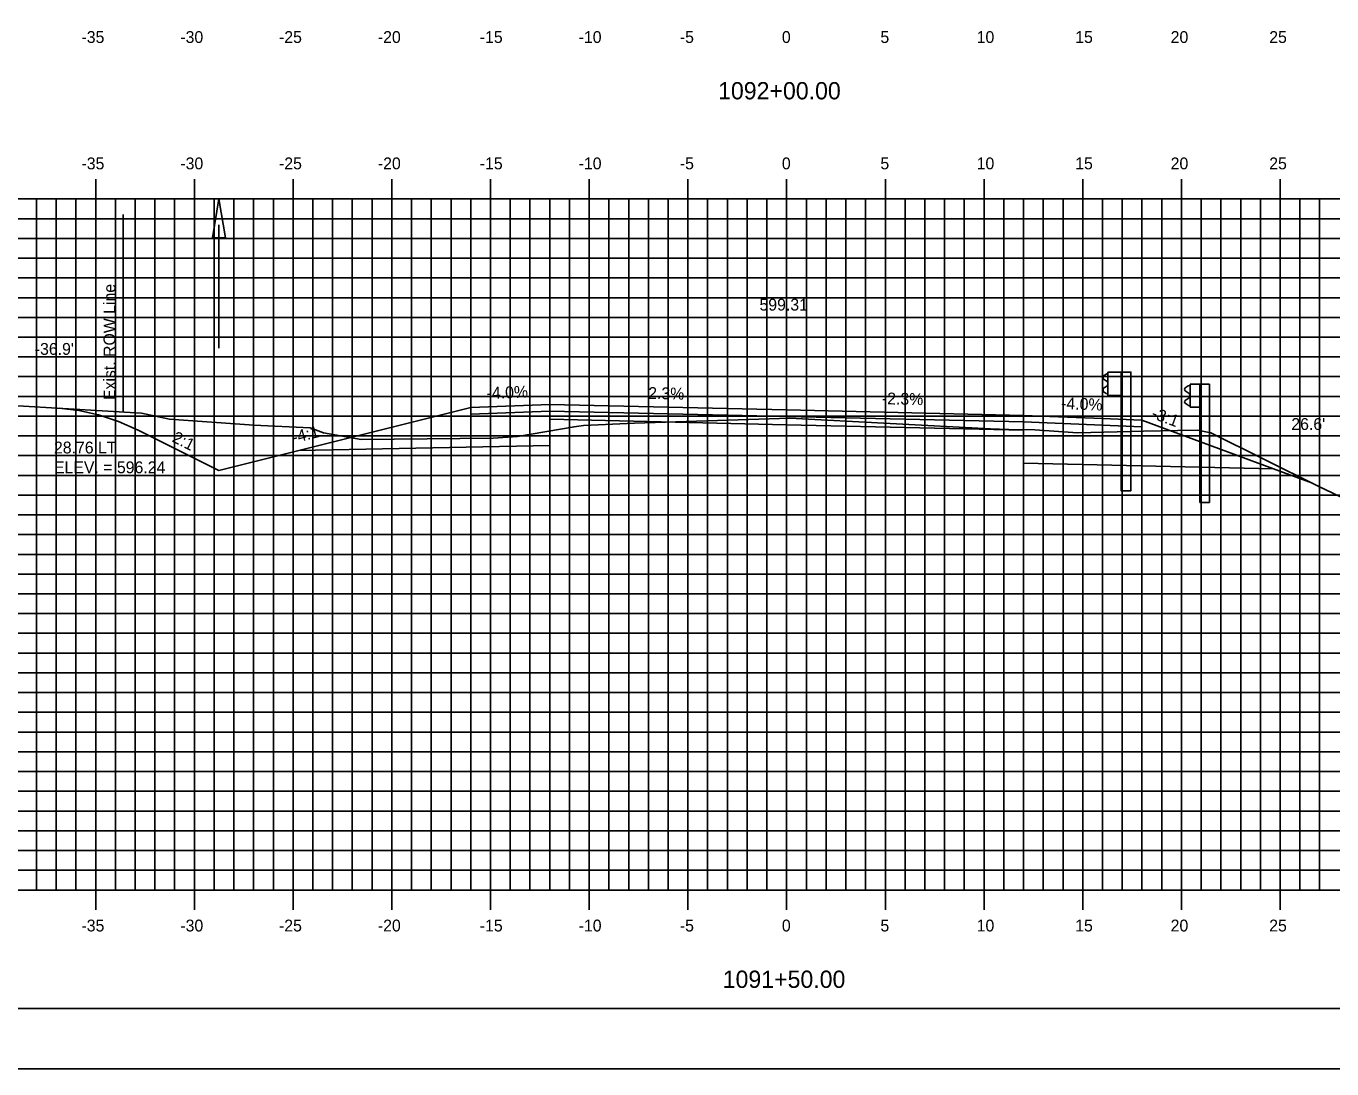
# Model space of a CAD drawing. Extents: x 1073864 to 1074034, y 779716 to 779826.
# Drawn here: x 1073908.9 to 1073975.1, y 779715.6 to 779768.5 of the extents above; entities that cross this region are included whole.
import ezdxf

# ---------------------------------------------------------------- set-up
doc = ezdxf.new("R2010")
doc.units = 0
for name, color, linetype in [('ANNOTATION', 7, 'Continuous'), ('BORDER', 7, 'Continuous'), ('D_Drainage_Ditch_Line', 7, 'Continuous'), ('D_Guardrail_Beam_Rt', 7, 'Continuous'), ('D_Roadway_Centerline', 7, 'Continuous'), ('D_Roadway_Centerline_Text', 7, 'Continuous'), ('D_Roadway_Edge_Pavement', 7, 'Continuous'), ('D_Roadway_Edge_Shoulder', 7, 'Continuous'), ('D_Roadway_Pavement', 7, 'Continuous'), ('D_Roadway_SlopeLines', 7, 'Continuous'), ('D_Roadway_SubGrade', 7, 'Continuous'), ('D_Text_Standard', 7, 'Continuous'), ('E_ROW_Line', 7, 'Continuous'), ('H_V ANNOTATION', 7, 'Continuous'), ('M_Guardrail', 7, 'Continuous'), ('MAJOR', 7, 'Continuous'), ('MINOR', 7, 'Continuous'), ('PLOT BOUNDARY', 7, 'Continuous'), ('S_Guardrail_Beam', 7, 'Continuous'), ('S_Roadway_Centerline', 7, 'Continuous')]:
    doc.layers.add(name, color=color, linetype=linetype)

msp = doc.modelspace()

# ---------------------------------------------------------------- linework, layer by layer
at = {"layer": 'BORDER'}
msp.add_lwpolyline([(1073872.472, 779718.706), (1074032.472, 779718.706), (1074032.472, 779823.706), (1073872.472, 779823.706)], close=True, dxfattribs=at)
at = {"layer": 'D_Drainage_Ditch_Line'}
msp.add_line((1073918.712, 779758.393), (1073918.712, 779752.15), dxfattribs=at)
msp.add_lwpolyline([(1073919.04, 779757.737), (1073918.384, 779757.737), (1073918.712, 779759.706)], close=True, dxfattribs=at)
at = {"layer": 'D_Guardrail_Beam_Rt'}
msp.add_lwpolyline([(1073963.751, 779750.856), (1073963.669, 779750.841), (1073963.652, 779750.834), (1073963.509, 779750.734), (1073963.509, 779750.591), (1073963.704, 779750.454), (1073963.738, 779750.39), (1073963.738, 779750.299), (1073963.704, 779750.234), (1073963.509, 779750.098), (1073963.509, 779749.954), (1073963.652, 779749.854), (1073963.669, 779749.847), (1073963.751, 779749.833)], dxfattribs=at)
for points in [[(1073963.751, 779750.935), (1073964.417, 779750.935), (1073964.417, 779749.754), (1073963.751, 779749.754)], [(1073964.417, 779750.935), (1073964.91, 779750.935), (1073964.91, 779744.931), (1073964.417, 779744.931)]]:
    msp.add_lwpolyline(points, close=True, dxfattribs=at)
at = {"layer": 'D_Roadway_Centerline'}
for points in [[(1073931.472, 779749.136), (1073935.472, 779749.296), (1073947.472, 779749.02), (1073959.472, 779748.744), (1073963.472, 779748.584), (1073965.472, 779748.504)], [(1073918.712, 779745.946), (1073922.762, 779746.958)]]:
    msp.add_lwpolyline(points, dxfattribs=at)
at = {"layer": 'D_Roadway_Edge_Pavement'}
msp.add_lwpolyline([(1073935.472, 779748.962), (1073935.472, 779749.296), (1073947.472, 779749.02), (1073959.472, 779748.744), (1073959.472, 779748.41), (1073947.472, 779748.686)], close=True, dxfattribs=at)
at = {"layer": 'D_Roadway_Edge_Shoulder'}
msp.add_lwpolyline([(1073935.472, 779749.296), (1073931.472, 779749.136), (1073931.472, 779748.802), (1073935.472, 779748.962)], close=True, dxfattribs=at)
msp.add_lwpolyline([(1073959.472, 779748.744), (1073963.472, 779748.584), (1073965.472, 779748.504), (1073965.472, 779748.17), (1073959.472, 779748.41), (1073959.472, 779748.744)], dxfattribs=at)
at = {"layer": 'D_Roadway_Pavement'}
msp.add_lwpolyline([(1073935.472, 779748.546), (1073935.472, 779748.962), (1073947.472, 779748.686), (1073959.472, 779748.41), (1073959.472, 779747.994), (1073947.472, 779748.27)], close=True, dxfattribs=at)
msp.add_lwpolyline([(1073935.472, 779748.962), (1073935.472, 779748.546)], dxfattribs=at)
at = {"layer": 'D_Roadway_SlopeLines'}
for points in [[(1073918.712, 779745.946), (1073914.62, 779747.992), (1073913.62, 779748.437), (1073912.62, 779748.771), (1073911.62, 779748.996), (1073910.62, 779749.11)], [(1073935.472, 779749.296), (1073931.472, 779749.136)], [(1073965.472, 779748.504), (1073972.136, 779746.036), (1073974.106, 779745.306)]]:
    msp.add_lwpolyline(points, dxfattribs=at)
at = {"layer": 'D_Roadway_SubGrade'}
msp.add_lwpolyline([(1073935.472, 779748.962), (1073931.472, 779748.802), (1073931.472, 779749.136), (1073922.762, 779746.958), (1073935.472, 779747.212), (1073935.472, 779748.962)], close=True, dxfattribs=at)
msp.add_lwpolyline([(1073972.136, 779746.036), (1073959.472, 779746.327), (1073959.472, 779746.91), (1073959.472, 779748.41), (1073959.472, 779748.41), (1073965.472, 779748.17), (1073965.472, 779748.504)], dxfattribs=at)
at = {"layer": 'E_ROW_Line'}
msp.add_line((1073913.87, 779748.918), (1073913.87, 779758.918), dxfattribs=at)
msp.add_line((1073913.87, 779748.918), (1073913.87, 779758.918), dxfattribs=at)
at = {"layer": 'M_Guardrail'}
for p, q in [((1073968.397, 779750.328), (1073968.888, 779750.328)), ((1073968.888, 779750.328), (1073968.888, 779744.328)), ((1073968.397, 779744.328), (1073968.397, 779749.161)), ((1073968.397, 779744.328), (1073968.888, 779744.328))]:
    msp.add_line(p, q, dxfattribs=at)
at = {"layer": 'MAJOR'}
for p, q in [((1073912.472, 779760.708), (1073912.472, 779759.706)), ((1073917.472, 779760.708), (1073917.472, 779759.706)), ((1073922.472, 779760.708), (1073922.472, 779759.706)), ((1073927.472, 779760.708), (1073927.472, 779759.706)), ((1073932.472, 779760.708), (1073932.472, 779759.706)), ((1073937.472, 779760.708), (1073937.472, 779759.706)), ((1073942.472, 779760.708), (1073942.472, 779759.706)), ((1073947.472, 779760.708), (1073947.472, 779759.706)), ((1073952.472, 779760.708), (1073952.472, 779759.706)), ((1073957.472, 779760.708), (1073957.472, 779759.706)), ((1073962.472, 779760.708), (1073962.472, 779759.706)), ((1073967.472, 779760.708), (1073967.472, 779759.706)), ((1073972.472, 779760.708), (1073972.472, 779759.706)), ((1073877.472, 779759.706), (1074017.472, 779759.706)), ((1073877.472, 779759.706), (1074017.472, 779759.706)), ((1073912.472, 779724.706), (1073912.472, 779759.706)), ((1073917.472, 779724.706), (1073917.472, 779759.706)), ((1073922.472, 779724.706), (1073922.472, 779759.706)), ((1073927.472, 779724.706), (1073927.472, 779759.706)), ((1073932.472, 779724.706), (1073932.472, 779759.706)), ((1073937.472, 779724.706), (1073937.472, 779759.706)), ((1073942.472, 779724.706), (1073942.472, 779759.706)), ((1073947.472, 779724.706), (1073947.472, 779759.706)), ((1073952.472, 779724.706), (1073952.472, 779759.706)), ((1073957.472, 779724.706), (1073957.472, 779759.706)), ((1073962.472, 779724.706), (1073962.472, 779759.706)), ((1073967.472, 779724.706), (1073967.472, 779759.706)), ((1073972.472, 779724.706), (1073972.472, 779759.706)), ((1073877.472, 779754.706), (1074017.472, 779754.706)), ((1073877.472, 779749.706), (1074017.472, 779749.706)), ((1073877.472, 779744.706), (1074017.472, 779744.706)), ((1073877.472, 779739.706), (1074017.472, 779739.706)), ((1073877.472, 779734.706), (1074017.472, 779734.706)), ((1073877.472, 779729.706), (1074017.472, 779729.706)), ((1073877.472, 779724.706), (1074017.472, 779724.706)), ((1073877.472, 779724.706), (1074017.472, 779724.706)), ((1073912.472, 779723.704), (1073912.472, 779724.706)), ((1073917.472, 779723.704), (1073917.472, 779724.706)), ((1073922.472, 779723.704), (1073922.472, 779724.706)), ((1073927.472, 779723.704), (1073927.472, 779724.706)), ((1073932.472, 779723.704), (1073932.472, 779724.706)), ((1073937.472, 779723.704), (1073937.472, 779724.706)), ((1073942.472, 779723.704), (1073942.472, 779724.706)), ((1073947.472, 779723.704), (1073947.472, 779724.706)), ((1073952.472, 779723.704), (1073952.472, 779724.706)), ((1073957.472, 779723.704), (1073957.472, 779724.706)), ((1073962.472, 779723.704), (1073962.472, 779724.706)), ((1073967.472, 779723.704), (1073967.472, 779724.706)), ((1073972.472, 779723.704), (1073972.472, 779724.706))]:
    msp.add_line(p, q, dxfattribs=at)
at = {"layer": 'MINOR'}
for p, q in [((1073909.472, 779724.706), (1073909.472, 779759.706)), ((1073910.472, 779724.706), (1073910.472, 779759.706)), ((1073911.472, 779724.706), (1073911.472, 779759.706)), ((1073913.472, 779724.706), (1073913.472, 779759.706)), ((1073914.472, 779724.706), (1073914.472, 779759.706)), ((1073915.472, 779724.706), (1073915.472, 779759.706)), ((1073916.472, 779724.706), (1073916.472, 779759.706)), ((1073918.472, 779724.706), (1073918.472, 779759.706)), ((1073919.472, 779724.706), (1073919.472, 779759.706)), ((1073920.472, 779724.706), (1073920.472, 779759.706)), ((1073921.472, 779724.706), (1073921.472, 779759.706)), ((1073923.472, 779724.706), (1073923.472, 779759.706)), ((1073924.472, 779724.706), (1073924.472, 779759.706)), ((1073925.472, 779724.706), (1073925.472, 779759.706)), ((1073926.472, 779724.706), (1073926.472, 779759.706)), ((1073928.472, 779724.706), (1073928.472, 779759.706)), ((1073929.472, 779724.706), (1073929.472, 779759.706)), ((1073930.472, 779724.706), (1073930.472, 779759.706)), ((1073931.472, 779724.706), (1073931.472, 779759.706)), ((1073933.472, 779724.706), (1073933.472, 779759.706)), ((1073934.472, 779724.706), (1073934.472, 779759.706)), ((1073935.472, 779724.706), (1073935.472, 779759.706)), ((1073936.472, 779724.706), (1073936.472, 779759.706)), ((1073938.472, 779724.706), (1073938.472, 779759.706)), ((1073939.472, 779724.706), (1073939.472, 779759.706)), ((1073940.472, 779724.706), (1073940.472, 779759.706)), ((1073941.472, 779724.706), (1073941.472, 779759.706)), ((1073943.472, 779724.706), (1073943.472, 779759.706)), ((1073944.472, 779724.706), (1073944.472, 779759.706)), ((1073945.472, 779724.706), (1073945.472, 779759.706)), ((1073946.472, 779724.706), (1073946.472, 779759.706)), ((1073948.472, 779724.706), (1073948.472, 779759.706)), ((1073949.472, 779724.706), (1073949.472, 779759.706)), ((1073950.472, 779724.706), (1073950.472, 779759.706)), ((1073951.472, 779724.706), (1073951.472, 779759.706)), ((1073953.472, 779724.706), (1073953.472, 779759.706)), ((1073954.472, 779724.706), (1073954.472, 779759.706)), ((1073955.472, 779724.706), (1073955.472, 779759.706)), ((1073956.472, 779724.706), (1073956.472, 779759.706)), ((1073958.472, 779724.706), (1073958.472, 779759.706)), ((1073959.472, 779724.706), (1073959.472, 779759.706)), ((1073960.472, 779724.706), (1073960.472, 779759.706)), ((1073961.472, 779724.706), (1073961.472, 779759.706)), ((1073963.472, 779724.706), (1073963.472, 779759.706)), ((1073964.472, 779724.706), (1073964.472, 779759.706)), ((1073965.472, 779724.706), (1073965.472, 779759.706)), ((1073966.472, 779724.706), (1073966.472, 779759.706)), ((1073968.472, 779724.706), (1073968.472, 779759.706)), ((1073969.472, 779724.706), (1073969.472, 779759.706)), ((1073970.472, 779724.706), (1073970.472, 779759.706)), ((1073971.472, 779724.706), (1073971.472, 779759.706)), ((1073973.472, 779724.706), (1073973.472, 779759.706)), ((1073974.472, 779724.706), (1073974.472, 779759.706)), ((1073877.472, 779758.706), (1074017.472, 779758.706)), ((1073877.472, 779757.706), (1074017.472, 779757.706)), ((1073877.472, 779756.706), (1074017.472, 779756.706)), ((1073877.472, 779755.706), (1074017.472, 779755.706)), ((1073877.472, 779753.706), (1074017.472, 779753.706)), ((1073877.472, 779752.706), (1074017.472, 779752.706)), ((1073877.472, 779751.706), (1074017.472, 779751.706)), ((1073877.472, 779750.706), (1074017.472, 779750.706)), ((1073877.472, 779748.706), (1074017.472, 779748.706)), ((1073877.472, 779747.706), (1074017.472, 779747.706)), ((1073877.472, 779746.706), (1074017.472, 779746.706)), ((1073877.472, 779745.706), (1074017.472, 779745.706)), ((1073877.472, 779743.706), (1074017.472, 779743.706)), ((1073877.472, 779742.706), (1074017.472, 779742.706)), ((1073877.472, 779741.706), (1074017.472, 779741.706)), ((1073877.472, 779740.706), (1074017.472, 779740.706)), ((1073877.472, 779738.706), (1074017.472, 779738.706)), ((1073877.472, 779737.706), (1074017.472, 779737.706)), ((1073877.472, 779736.706), (1074017.472, 779736.706)), ((1073877.472, 779735.706), (1074017.472, 779735.706)), ((1073877.472, 779733.706), (1074017.472, 779733.706)), ((1073877.472, 779732.706), (1074017.472, 779732.706)), ((1073877.472, 779731.706), (1074017.472, 779731.706)), ((1073877.472, 779730.706), (1074017.472, 779730.706)), ((1073877.472, 779728.706), (1074017.472, 779728.706)), ((1073877.472, 779727.706), (1074017.472, 779727.706)), ((1073877.472, 779726.706), (1074017.472, 779726.706)), ((1073877.472, 779725.706), (1074017.472, 779725.706))]:
    msp.add_line(p, q, dxfattribs=at)
at = {"layer": 'PLOT BOUNDARY'}
msp.add_lwpolyline([(1073864.379, 779715.646), (1074034.379, 779715.646), (1074034.379, 779825.646), (1073864.379, 779825.646)], close=True, dxfattribs=at)
at = {"layer": 'S_Guardrail_Beam'}
for p, q in [((1073967.808, 779750.233), (1073967.665, 779750.133)), ((1073967.665, 779749.99), (1073967.86, 779749.854)), ((1073967.907, 779750.255), (1073967.825, 779750.24)), ((1073967.894, 779749.79), (1073967.894, 779749.699)), ((1073967.907, 779750.328), (1073968.397, 779750.328)), ((1073967.907, 779749.161), (1073967.907, 779750.328)), ((1073968.397, 779750.328), (1073968.397, 779749.161)), ((1073967.86, 779749.634), (1073967.665, 779749.498)), ((1073967.665, 779749.355), (1073967.808, 779749.255)), ((1073967.825, 779749.248), (1073967.907, 779749.234)), ((1073968.397, 779749.161), (1073967.907, 779749.161))]:
    msp.add_line(p, q, dxfattribs=at)
for centre, major_axis, start_param, end_param in [((1073967.715, 779750.062), (-0.0877, 0), 5.323254, 7.243116), ((1073967.832, 779750.199), (-0.0417, 0), 4.886922, 5.323254), ((1073967.815, 779749.79), (0.0789, 0), 0, 0.959931), ((1073967.715, 779749.427), (-0.0877, 0), 5.323254, 7.243116), ((1073967.832, 779749.289), (-0.0417, 0), 0.959931, 1.396263), ((1073967.815, 779749.699), (0.0789, 0), 5.323254, 6.283185)]:
    msp.add_ellipse(centre, major_axis=major_axis, ratio=0.995501, start_param=start_param, end_param=end_param, dxfattribs=at)
at = {"layer": 'S_Roadway_Centerline'}
msp.add_lwpolyline([(1073904.533, 779749.471), (1073914.788, 779748.863), (1073916.211, 779748.547), (1073920.478, 779748.242), (1073923.328, 779748.111), (1073924.02, 779747.856), (1073925.926, 779747.518), (1073932.605, 779747.586), (1073933.837, 779747.676), (1073936.707, 779748.172), (1073937.176, 779748.23), (1073939.761, 779748.354), (1073947.627, 779748.608), (1073957.794, 779748.061), (1073958.725, 779748.022), (1073960.038, 779748.007), (1073962.204, 779747.86), (1073965.558, 779747.948), (1073967.285, 779747.985), (1073968.281, 779747.996), (1073968.961, 779747.853), (1073974.39, 779745.165), (1073985.616, 779739.805)], dxfattribs=at)

# ---------------------------------------------------------------- texts
at = {"layer": 'ANNOTATION'}
for s, rotation, p in [('-4.0%', 2.29061, (1073932.288, 779749.569)), ('2.3%', 358.68243, (1073940.452, 779749.581)), ('-2.3%', 358.68243, (1073952.292, 779749.309)), ('-4.0%', 357.70939, (1073961.368, 779749.069)), ('-3:1', 339.67686, (1073965.903, 779748.623)), ('2:1', 333.43495, (1073916.298, 779747.432)), ('-4:1', 14.03624, (1073922.499, 779747.323))]:
    msp.add_text(s, height=0.6, rotation=rotation, dxfattribs=at).set_placement(p)
for s, p in [('28.76 LT', (1073910.358, 779746.815)), ('ELEV. = 596.24', (1073910.358, 779745.813))]:
    msp.add_text(s, height=0.6, dxfattribs=at).set_placement(p)
at = {"layer": 'D_Roadway_Centerline_Text'}
msp.add_text('599.31', height=0.6, dxfattribs=at).set_placement((1073946.097, 779754.052))
at = {"layer": 'D_Text_Standard'}
for s, p in [("-36.9'", (1073909.387, 779751.81)), ("26.6'", (1073973.038, 779748.006))]:
    msp.add_text(s, height=0.6, dxfattribs=at).set_placement(p)
at = {"layer": 'E_ROW_Line'}
msp.add_text('Exist. ROW Line', height=0.6, rotation=90, dxfattribs=at).set_placement((1073913.47, 779749.518))
at = {"layer": 'H_V ANNOTATION'}
for s, height, p in [('-35', 0.6, (1073911.752, 779767.606)), ('-30', 0.6, (1073916.76, 779767.606)), ('-25', 0.6, (1073921.758, 779767.606)), ('-20', 0.6, (1073926.766, 779767.606)), ('-15', 0.6, (1073931.929, 779767.606)), ('-10', 0.6, (1073936.937, 779767.606)), ('-5', 0.6, (1073942.063, 779767.606)), ('0', 0.6, (1073947.231, 779767.606)), ('5', 0.6, (1073952.223, 779767.606)), ('10', 0.6, (1073957.098, 779767.606)), ('15', 0.6, (1073962.09, 779767.606)), ('20', 0.6, (1073966.926, 779767.606)), ('25', 0.6, (1073971.918, 779767.606)), ('1092+00.00', 0.875, (1073944, 779764.749)), ('-35', 0.6, (1073911.752, 779761.206)), ('-30', 0.6, (1073916.76, 779761.206)), ('-25', 0.6, (1073921.758, 779761.206)), ('-20', 0.6, (1073926.766, 779761.206)), ('-15', 0.6, (1073931.929, 779761.206)), ('-10', 0.6, (1073936.937, 779761.206)), ('-5', 0.6, (1073942.063, 779761.206)), ('0', 0.6, (1073947.231, 779761.206)), ('5', 0.6, (1073952.223, 779761.206)), ('10', 0.6, (1073957.098, 779761.206)), ('15', 0.6, (1073962.09, 779761.206)), ('20', 0.6, (1073966.926, 779761.206)), ('25', 0.6, (1073971.918, 779761.206)), ('-35', 0.6, (1073911.752, 779722.606)), ('-30', 0.6, (1073916.76, 779722.606)), ('-25', 0.6, (1073921.758, 779722.606)), ('-20', 0.6, (1073926.766, 779722.606)), ('-15', 0.6, (1073931.929, 779722.606)), ('-10', 0.6, (1073936.937, 779722.606)), ('-5', 0.6, (1073942.063, 779722.606)), ('0', 0.6, (1073947.231, 779722.606)), ('5', 0.6, (1073952.223, 779722.606)), ('10', 0.6, (1073957.098, 779722.606)), ('15', 0.6, (1073962.09, 779722.606)), ('20', 0.6, (1073966.926, 779722.606)), ('25', 0.6, (1073971.918, 779722.606)), ('1091+50.00', 0.875, (1073944.234, 779719.749))]:
    msp.add_text(s, height=height, dxfattribs=at).set_placement(p)

doc.saveas('drawing.dxf')
